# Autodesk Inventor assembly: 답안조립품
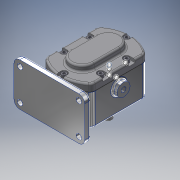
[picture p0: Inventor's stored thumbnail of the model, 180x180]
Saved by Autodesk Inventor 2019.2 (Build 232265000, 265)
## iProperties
Created: 2019-03
Part Number: 답안조립품
Material: 일반
Document SubType Name: Assembly
Designer: User
Author: User
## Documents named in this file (11)
- C:\Users\User\Desktop\490307V1032\답안조립품.iam
- C:\Users\User\Desktop\490307V1032\본체.ipt
- C:\Users\User\Desktop\490307V1032\오일 실 16 28 7.ipt
- C:\Users\User\Desktop\490307V1032\베어링부시.ipt
- C:\Users\User\Desktop\490307V1032\서브축.ipt
- C:\Users\User\Desktop\490307V1032\키 6 x 6 x 18.ipt
- C:\Users\User\Desktop\490307V1032\스퍼기어.ipt
- C:\Users\User\Desktop\490307V1032\메인축.ipt
- C:\Users\User\Desktop\490307V1032\개스킷.ipt
- C:\Users\User\Desktop\490307V1032\커버.ipt
- C:\Users\User\Desktop\490307V1032\볼트 M5.ipt
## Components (1 placed, 1 different names)
1. 개스킷:1
